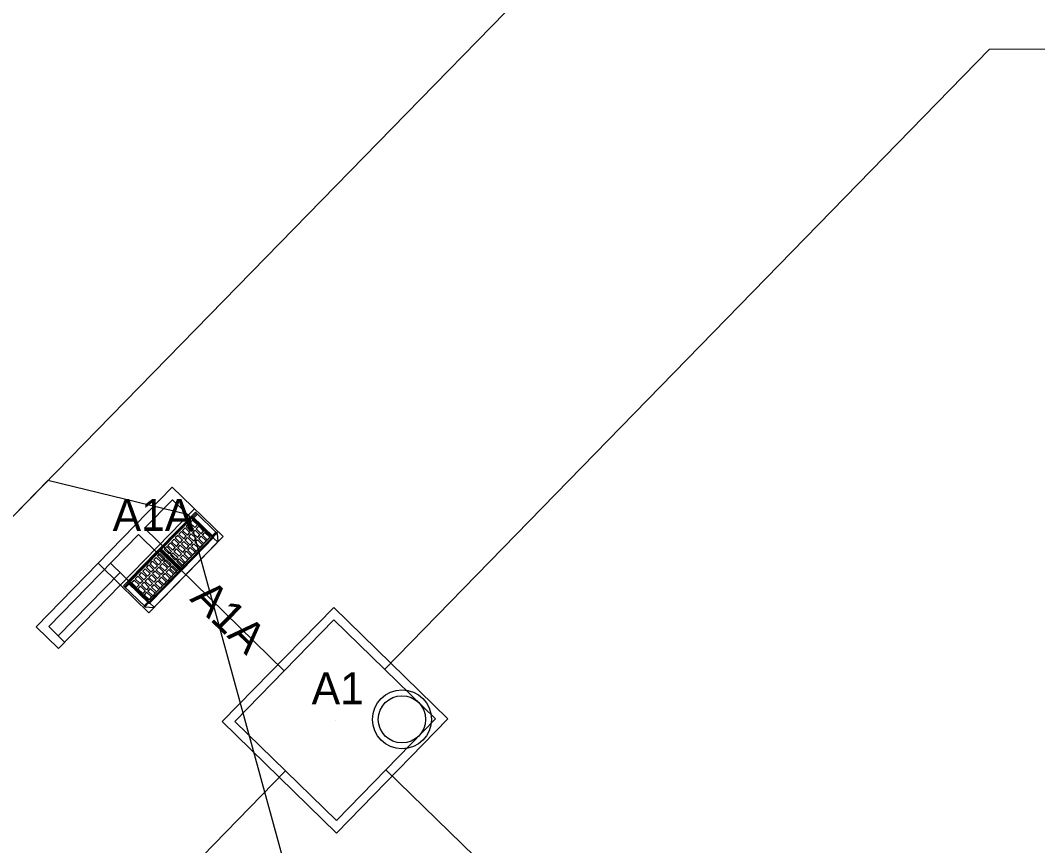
# Model space of a CAD drawing. Extents: x 2252703 to 2264864, y 13787568 to 13790989.
# Drawn here: x 2254977.3 to 2255034.7, y 13790882.1 to 13790928.6 of the extents above; entities that cross this region are included whole.
import ezdxf

# ---------------------------------------------------------------- set-up
doc = ezdxf.new("R2010")
doc.units = 0
for name, color, linetype in [('D_BOXES_1', 7, 'Continuous'), ('D_DRAIN_MISC', 7, 'Continuous'), ('D_DRAIN_NOTES_1', 7, 'Continuous'), ('D_DRN_AREA_X', 7, 'Continuous'), ('D_DRN_PIPE', 7, 'Continuous'), ('D_INLET_1', 7, 'Continuous'), ('D_PIPES_1', 7, 'Continuous')]:
    doc.layers.add(name, color=color, linetype=linetype)

msp = doc.modelspace()

# ---------------------------------------------------------------- linework, layer by layer
at = {"layer": 'D_BOXES_1'}
msp.add_line((2254879.145, 13790770.287), (2254992.252, 13790886.265), dxfattribs=at)
msp.add_lwpolyline([(2254997.838, 13790891.992), (2255031.955, 13790926.975), (2255102.297, 13790927.278)], dxfattribs=at)
at = {"layer": 'D_DRAIN_MISC'}
for p, q in [((2254986.947, 13790900.518), (2254986.947, 13790900.518)), ((2254984.127, 13790899.776), (2254984.127, 13790899.776)), ((2254985.022, 13790898.903), (2254985.022, 13790898.903)), ((2254986.275, 13790897.681), (2254986.275, 13790897.681)), ((2254983.456, 13790896.939), (2254983.456, 13790896.939)), ((2254992.181, 13790891.921), (2254992.181, 13790891.921)), ((2254997.838, 13790891.992), (2254997.838, 13790891.992)), ((2254995.045, 13790889.128), (2254995.045, 13790889.128)), ((2254992.252, 13790886.265), (2254992.252, 13790886.265)), ((2254997.909, 13790886.336), (2254997.909, 13790886.336))]:
    msp.add_line(p, q, dxfattribs=at)
at = {"layer": 'D_DRN_AREA_X'}
for p, q in [((2254998.27, 13790922.513), (2255013.601, 13790938.233)), ((2254982.407, 13790906.289), (2254998.27, 13790922.513)), ((2254976.227, 13790899.968), (2254982.409, 13790906.286)), ((2254978.85, 13790902.651), (2254976.227, 13790899.968)), ((2254986.79, 13790900.715), (2254978.85, 13790902.651)), ((2254993.845, 13790875.008), (2254986.79, 13790900.715))]:
    msp.add_line(p, q, dxfattribs=at)
at = {"layer": 'D_DRN_PIPE'}
msp.add_lwpolyline([(2254997.838, 13790891.992), (2255031.955, 13790926.975), (2255102.297, 13790927.278)], dxfattribs=at)
msp.add_lwpolyline([(2254997.838, 13790891.992), (2255031.955, 13790926.975), (2255102.297, 13790927.278)], dxfattribs=at)
at = {"layer": 'D_INLET_1'}
for p, q in [((2254985.864, 13790902.273), (2254978.184, 13790894.397)), ((2254988.728, 13790899.48), (2254985.864, 13790902.273)), ((2254985.873, 13790901.565), (2254984.302, 13790899.955)), ((2254988.021, 13790899.471), (2254985.873, 13790901.565)), ((2254987.117, 13790901.051), (2254979.437, 13790893.176)), ((2254987.165, 13790900.864), (2254984.073, 13790897.694)), ((2254986.987, 13790900.63), (2254985.18, 13790898.778)), ((2254986.992, 13790900.567), (2254985.243, 13790898.775)), ((2254986.989, 13790900.548), (2254985.263, 13790898.778)), ((2254987, 13790900.406), (2254986.858, 13790900.26)), ((2254988.204, 13790899.443), (2254986.987, 13790900.63)), ((2254988.122, 13790899.443), (2254986.989, 13790900.548)), ((2254988.141, 13790899.446), (2254986.992, 13790900.567)), ((2254987.275, 13790900.138), (2254987, 13790900.406)), ((2254987.021, 13790900.597), (2254987.225, 13790900.806)), ((2254987.072, 13790900.547), (2254987.276, 13790900.756)), ((2254988.395, 13790899.665), (2254987.165, 13790900.864)), ((2254988.427, 13790899.773), (2254984.238, 13790895.478)), ((2254984.302, 13790899.955), (2254986.507, 13790897.804)), ((2254986.378, 13790899.767), (2254986.235, 13790899.622)), ((2254986.378, 13790899.767), (2254986.652, 13790899.499)), ((2254986.585, 13790899.98), (2254986.443, 13790899.834)), ((2254986.443, 13790899.834), (2254986.718, 13790899.567)), ((2254986.585, 13790899.98), (2254986.86, 13790899.712)), ((2254986.793, 13790900.193), (2254986.651, 13790900.047)), ((2254986.651, 13790900.047), (2254986.925, 13790899.779)), ((2254986.793, 13790900.193), (2254987.067, 13790899.925)), ((2254986.858, 13790900.26), (2254987.133, 13790899.992)), ((2254986.925, 13790899.779), (2254987.067, 13790899.925)), ((2254987.002, 13790899.705), (2254987.144, 13790899.85)), ((2254987.133, 13790899.992), (2254987.275, 13790900.138)), ((2254987.144, 13790899.85), (2254987.421, 13790899.581)), ((2254987.21, 13790899.918), (2254987.352, 13790900.063)), ((2254987.21, 13790899.918), (2254987.486, 13790899.648)), ((2254987.628, 13790899.793), (2254987.352, 13790900.063)), ((2254987.486, 13790899.648), (2254987.628, 13790899.793)), ((2254983.953, 13790899.597), (2254978.891, 13790894.406)), ((2254983.953, 13790899.597), (2254986.158, 13790897.446)), ((2254988.021, 13790899.471), (2254984.53, 13790895.891)), ((2254988.725, 13790899.483), (2254984.536, 13790895.187)), ((2254988.728, 13790899.48), (2254984.539, 13790895.184)), ((2254988.439, 13790899.189), (2254984.822, 13790895.48)), ((2254985.962, 13790899.341), (2254985.82, 13790899.196)), ((2254985.82, 13790899.196), (2254986.095, 13790898.928)), ((2254985.962, 13790899.341), (2254986.237, 13790899.074)), ((2254986.17, 13790899.554), (2254986.028, 13790899.409)), ((2254986.028, 13790899.409), (2254986.302, 13790899.141)), ((2254986.17, 13790899.554), (2254986.445, 13790899.287)), ((2254986.235, 13790899.622), (2254986.51, 13790899.354)), ((2254986.302, 13790899.141), (2254986.445, 13790899.287)), ((2254986.379, 13790899.066), (2254986.521, 13790899.212)), ((2254988.141, 13790899.446), (2254986.393, 13790897.654)), ((2254986.395, 13790897.673), (2254988.122, 13790899.443)), ((2254988.204, 13790899.443), (2254986.398, 13790897.591)), ((2254986.51, 13790899.354), (2254986.652, 13790899.499)), ((2254986.521, 13790899.212), (2254986.798, 13790898.942)), ((2254988.109, 13790899.39), (2254986.536, 13790897.777)), ((2254986.587, 13790899.279), (2254986.729, 13790899.425)), ((2254986.587, 13790899.279), (2254986.863, 13790899.009)), ((2254986.718, 13790899.567), (2254986.86, 13790899.712)), ((2254986.729, 13790899.425), (2254987.005, 13790899.155)), ((2254986.794, 13790899.492), (2254986.936, 13790899.638)), ((2254986.794, 13790899.492), (2254987.071, 13790899.222)), ((2254986.936, 13790899.638), (2254987.213, 13790899.368)), ((2254987.002, 13790899.705), (2254987.279, 13790899.435)), ((2254987.071, 13790899.222), (2254987.213, 13790899.368)), ((2254987.148, 13790899.147), (2254987.29, 13790899.293)), ((2254987.279, 13790899.435), (2254987.421, 13790899.581)), ((2254987.29, 13790899.293), (2254987.564, 13790899.025)), ((2254987.355, 13790899.36), (2254987.497, 13790899.506)), ((2254987.355, 13790899.36), (2254987.63, 13790899.092)), ((2254987.497, 13790899.506), (2254987.772, 13790899.238)), ((2254987.563, 13790899.573), (2254987.705, 13790899.719)), ((2254987.563, 13790899.573), (2254987.837, 13790899.305)), ((2254987.63, 13790899.092), (2254987.772, 13790899.238)), ((2254987.98, 13790899.451), (2254987.705, 13790899.719)), ((2254987.837, 13790899.305), (2254987.98, 13790899.451)), ((2254988.119, 13790899.526), (2254988.323, 13790899.735)), ((2254988.17, 13790899.476), (2254988.374, 13790899.685)), ((2254988.175, 13790899.413), (2254988.422, 13790899.172)), ((2254988.449, 13790899.221), (2254988.41, 13790899.634)), ((2254983.345, 13790896.896), (2254985.151, 13790898.748)), ((2254983.408, 13790896.892), (2254985.156, 13790898.685)), ((2254983.427, 13790896.895), (2254985.154, 13790898.666)), ((2254986.369, 13790897.561), (2254985.151, 13790898.748)), ((2254986.286, 13790897.561), (2254985.154, 13790898.666)), ((2254986.306, 13790897.564), (2254985.156, 13790898.685)), ((2254986.398, 13790897.591), (2254985.18, 13790898.778)), ((2254986.393, 13790897.654), (2254985.243, 13790898.775)), ((2254986.395, 13790897.673), (2254985.263, 13790898.778)), ((2254985.547, 13790898.916), (2254985.405, 13790898.77)), ((2254985.68, 13790898.502), (2254985.405, 13790898.77)), ((2254985.547, 13790898.916), (2254985.822, 13790898.648)), ((2254985.755, 13790899.129), (2254985.613, 13790898.983)), ((2254985.613, 13790898.983), (2254985.887, 13790898.715)), ((2254985.68, 13790898.502), (2254985.822, 13790898.648)), ((2254985.755, 13790899.129), (2254986.029, 13790898.861)), ((2254985.887, 13790898.715), (2254986.029, 13790898.861)), ((2254985.964, 13790898.64), (2254986.106, 13790898.786)), ((2254985.964, 13790898.64), (2254986.241, 13790898.371)), ((2254986.095, 13790898.928), (2254986.237, 13790899.074)), ((2254986.106, 13790898.786), (2254986.383, 13790898.516)), ((2254986.172, 13790898.853), (2254986.314, 13790898.999)), ((2254986.172, 13790898.853), (2254986.448, 13790898.583)), ((2254986.314, 13790898.999), (2254986.59, 13790898.729)), ((2254986.379, 13790899.066), (2254986.656, 13790898.796)), ((2254986.448, 13790898.583), (2254986.59, 13790898.729)), ((2254986.525, 13790898.509), (2254986.667, 13790898.654)), ((2254986.656, 13790898.796), (2254986.798, 13790898.942)), ((2254986.667, 13790898.654), (2254986.942, 13790898.387)), ((2254986.732, 13790898.722), (2254986.875, 13790898.867)), ((2254986.732, 13790898.722), (2254987.007, 13790898.454)), ((2254986.863, 13790899.009), (2254987.005, 13790899.155)), ((2254986.875, 13790898.867), (2254987.149, 13790898.599)), ((2254986.94, 13790898.934), (2254987.082, 13790899.08)), ((2254986.94, 13790898.934), (2254987.215, 13790898.667)), ((2254987.082, 13790899.08), (2254987.357, 13790898.812)), ((2254987.148, 13790899.147), (2254987.422, 13790898.879)), ((2254987.215, 13790898.667), (2254987.357, 13790898.812)), ((2254987.422, 13790898.879), (2254987.564, 13790899.025)), ((2254984.607, 13790897.952), (2254984.749, 13790898.098)), ((2254984.749, 13790898.098), (2254985.024, 13790897.83)), ((2254984.815, 13790898.165), (2254984.957, 13790898.311)), ((2254984.815, 13790898.165), (2254985.09, 13790897.897)), ((2254984.957, 13790898.311), (2254985.232, 13790898.043)), ((2254985.023, 13790898.378), (2254985.165, 13790898.524)), ((2254985.023, 13790898.378), (2254985.297, 13790898.11)), ((2254985.232, 13790898.043), (2254985.09, 13790897.897)), ((2254985.439, 13790898.256), (2254985.165, 13790898.524)), ((2254985.439, 13790898.256), (2254985.297, 13790898.11)), ((2254985.516, 13790898.181), (2254985.374, 13790898.035)), ((2254985.793, 13790897.911), (2254985.516, 13790898.181)), ((2254985.756, 13790898.428), (2254985.898, 13790898.573)), ((2254986.033, 13790898.158), (2254985.756, 13790898.428)), ((2254985.898, 13790898.573), (2254986.175, 13790898.303)), ((2254986.033, 13790898.158), (2254986.175, 13790898.303)), ((2254986.11, 13790898.083), (2254986.252, 13790898.229)), ((2254986.384, 13790897.815), (2254986.11, 13790898.083)), ((2254986.241, 13790898.371), (2254986.383, 13790898.516)), ((2254986.252, 13790898.229), (2254986.526, 13790897.961)), ((2254986.317, 13790898.296), (2254986.459, 13790898.441)), ((2254986.317, 13790898.296), (2254986.592, 13790898.028)), ((2254986.459, 13790898.441), (2254986.734, 13790898.174)), ((2254986.525, 13790898.509), (2254986.799, 13790898.241)), ((2254986.592, 13790898.028), (2254986.734, 13790898.174)), ((2254986.799, 13790898.241), (2254986.942, 13790898.387)), ((2254987.007, 13790898.454), (2254987.149, 13790898.599)), ((2254982.928, 13790896.755), (2254981.675, 13790897.977)), ((2254984.53, 13790895.891), (2254982.382, 13790897.986)), ((2254984.073, 13790897.694), (2254983.115, 13790896.712)), ((2254984.192, 13790897.526), (2254984.334, 13790897.672)), ((2254984.192, 13790897.526), (2254984.467, 13790897.259)), ((2254984.334, 13790897.672), (2254984.609, 13790897.404)), ((2254984.4, 13790897.739), (2254984.542, 13790897.885)), ((2254984.4, 13790897.739), (2254984.674, 13790897.472)), ((2254984.542, 13790897.885), (2254984.816, 13790897.617)), ((2254984.557, 13790895.771), (2254986.306, 13790897.564)), ((2254986.286, 13790897.561), (2254984.56, 13790895.791)), ((2254984.562, 13790895.708), (2254986.369, 13790897.561)), ((2254984.607, 13790897.952), (2254984.882, 13790897.684)), ((2254984.816, 13790897.617), (2254984.674, 13790897.472)), ((2254984.893, 13790897.542), (2254984.751, 13790897.397)), ((2254985.024, 13790897.83), (2254984.882, 13790897.684)), ((2254984.893, 13790897.542), (2254985.17, 13790897.273)), ((2254985.101, 13790897.755), (2254984.959, 13790897.61)), ((2254984.959, 13790897.61), (2254985.235, 13790897.34)), ((2254985.101, 13790897.755), (2254985.377, 13790897.485)), ((2254985.308, 13790897.968), (2254985.166, 13790897.823)), ((2254985.166, 13790897.823), (2254985.443, 13790897.553)), ((2254985.377, 13790897.485), (2254985.235, 13790897.34)), ((2254985.308, 13790897.968), (2254985.585, 13790897.698)), ((2254985.374, 13790898.035), (2254985.651, 13790897.766)), ((2254985.585, 13790897.698), (2254985.443, 13790897.553)), ((2254985.662, 13790897.624), (2254985.52, 13790897.478)), ((2254985.52, 13790897.478), (2254985.794, 13790897.21)), ((2254985.793, 13790897.911), (2254985.651, 13790897.766)), ((2254985.662, 13790897.624), (2254985.936, 13790897.356)), ((2254985.869, 13790897.836), (2254985.727, 13790897.691)), ((2254985.727, 13790897.691), (2254986.002, 13790897.423)), ((2254986.144, 13790897.569), (2254985.869, 13790897.836)), ((2254986.144, 13790897.569), (2254986.002, 13790897.423)), ((2254986.384, 13790897.815), (2254986.526, 13790897.961)), ((2254982.919, 13790897.462), (2254979.428, 13790893.883)), ((2254984.562, 13790895.708), (2254983.345, 13790896.896)), ((2254984.557, 13790895.771), (2254983.408, 13790896.892)), ((2254984.56, 13790895.791), (2254983.427, 13790896.895)), ((2254983.569, 13790896.888), (2254983.711, 13790897.034)), ((2254983.711, 13790897.034), (2254983.986, 13790896.766)), ((2254983.777, 13790897.101), (2254983.919, 13790897.246)), ((2254983.777, 13790897.101), (2254984.052, 13790896.833)), ((2254983.919, 13790897.246), (2254984.194, 13790896.979)), ((2254983.985, 13790897.314), (2254984.127, 13790897.459)), ((2254983.985, 13790897.314), (2254984.259, 13790897.046)), ((2254984.194, 13790896.979), (2254984.052, 13790896.833)), ((2254984.127, 13790897.459), (2254984.401, 13790897.191)), ((2254984.27, 13790896.904), (2254984.128, 13790896.758)), ((2254984.401, 13790897.191), (2254984.259, 13790897.046)), ((2254984.27, 13790896.904), (2254984.547, 13790896.634)), ((2254984.478, 13790897.117), (2254984.336, 13790896.971)), ((2254984.336, 13790896.971), (2254984.613, 13790896.701)), ((2254984.609, 13790897.404), (2254984.467, 13790897.259)), ((2254984.478, 13790897.117), (2254984.755, 13790896.847)), ((2254984.686, 13790897.33), (2254984.543, 13790897.184)), ((2254984.543, 13790897.184), (2254984.82, 13790896.914)), ((2254986.186, 13790897.418), (2254984.613, 13790895.805)), ((2254984.686, 13790897.33), (2254984.962, 13790897.06)), ((2254984.751, 13790897.397), (2254985.028, 13790897.127)), ((2254984.962, 13790897.06), (2254984.82, 13790896.914)), ((2254985.039, 13790896.985), (2254984.897, 13790896.839)), ((2254985.17, 13790897.273), (2254985.028, 13790897.127)), ((2254985.039, 13790896.985), (2254985.313, 13790896.717)), ((2254985.246, 13790897.198), (2254985.104, 13790897.052)), ((2254985.104, 13790897.052), (2254985.379, 13790896.784)), ((2254985.246, 13790897.198), (2254985.521, 13790896.93)), ((2254985.454, 13790897.411), (2254985.312, 13790897.265)), ((2254985.312, 13790897.265), (2254985.587, 13790896.997)), ((2254985.521, 13790896.93), (2254985.379, 13790896.784)), ((2254985.454, 13790897.411), (2254985.729, 13790897.143)), ((2254985.729, 13790897.143), (2254985.587, 13790896.997)), ((2254985.936, 13790897.356), (2254985.794, 13790897.21)), ((2254984.539, 13790895.184), (2254982.928, 13790896.755)), ((2254984.345, 13790895.513), (2254983.115, 13790896.712)), ((2254983.379, 13790896.863), (2254983.175, 13790896.653)), ((2254983.43, 13790896.813), (2254983.226, 13790896.604)), ((2254983.844, 13790896.62), (2254983.569, 13790896.888)), ((2254983.986, 13790896.766), (2254983.844, 13790896.62)), ((2254984.063, 13790896.691), (2254983.921, 13790896.545)), ((2254984.197, 13790896.275), (2254983.921, 13790896.545)), ((2254984.063, 13790896.691), (2254984.339, 13790896.421)), ((2254984.128, 13790896.758), (2254984.405, 13790896.488)), ((2254984.339, 13790896.421), (2254984.197, 13790896.275)), ((2254984.416, 13790896.346), (2254984.274, 13790896.201)), ((2254984.547, 13790896.634), (2254984.405, 13790896.488)), ((2254984.416, 13790896.346), (2254984.691, 13790896.079)), ((2254984.624, 13790896.559), (2254984.482, 13790896.414)), ((2254984.482, 13790896.414), (2254984.756, 13790896.146)), ((2254984.755, 13790896.847), (2254984.613, 13790896.701)), ((2254984.624, 13790896.559), (2254984.898, 13790896.291)), ((2254984.831, 13790896.772), (2254984.689, 13790896.626)), ((2254984.689, 13790896.626), (2254984.964, 13790896.359)), ((2254984.831, 13790896.772), (2254985.106, 13790896.504)), ((2254984.897, 13790896.839), (2254985.171, 13790896.572)), ((2254985.106, 13790896.504), (2254984.964, 13790896.359)), ((2254985.313, 13790896.717), (2254985.171, 13790896.572)), ((2254984.477, 13790895.791), (2254984.273, 13790895.582)), ((2254984.549, 13790895.933), (2254984.274, 13790896.201)), ((2254984.528, 13790895.742), (2254984.324, 13790895.532)), ((2254984.691, 13790896.079), (2254984.549, 13790895.933)), ((2254984.898, 13790896.291), (2254984.756, 13790896.146)), ((2254984.79, 13790895.469), (2254984.376, 13790895.498)), ((2254984.591, 13790895.738), (2254984.838, 13790895.497)), ((2254988.682, 13790889.049), (2254994.965, 13790895.492)), ((2254994.965, 13790895.492), (2255001.408, 13790889.208)), ((2254989.389, 13790889.057), (2254994.974, 13790894.785)), ((2254994.974, 13790894.785), (2255000.701, 13790889.199)), ((2254978.184, 13790894.397), (2254979.437, 13790893.176)), ((2254978.891, 13790894.406), (2254979.786, 13790893.534)), ((2254995.125, 13790882.765), (2254988.682, 13790889.049)), ((2254995.116, 13790883.472), (2254989.389, 13790889.057)), ((2255000.701, 13790889.199), (2254995.116, 13790883.472)), ((2255001.408, 13790889.208), (2254995.125, 13790882.765))]:
    msp.add_line(p, q, dxfattribs=at)
for radius in [1.666, 1.333]:
    msp.add_circle((2254998.816, 13790889.176), radius, dxfattribs=at)
for centre, start_param, end_param in [((2254988.365, 13790899.636), 0.80294, 1.570796), ((2254988.405, 13790899.223), 0, 0.80294), ((2254984.374, 13790895.543), 4.712389, 5.480245), ((2254984.787, 13790895.513), 5.480245, 6.283185)]:
    msp.add_ellipse(centre, major_axis=(0.0341, -0.0332), ratio=0.877193, start_param=start_param, end_param=end_param, dxfattribs=at)
at = {"layer": 'D_PIPES_1'}
for p, q in [((2254986.275, 13790897.681), (2254992.181, 13790891.921)), ((2255016.702, 13790868.008), (2254997.909, 13790886.336))]:
    msp.add_line(p, q, dxfattribs=at)

# ---------------------------------------------------------------- texts
at = {"layer": 'D_DRAIN_NOTES_1'}
for s, p in [('A1A', (2254982.5, 13790899.803)), ('A1', (2254993.723, 13790890.028))]:
    msp.add_text(s, height=1.8, dxfattribs=at).set_placement(p)
msp.add_text('A1A', height=1.8, rotation=315.71793, dxfattribs=at).set_placement((2254986.794, 13790895.918))

doc.saveas('drawing.dxf')
